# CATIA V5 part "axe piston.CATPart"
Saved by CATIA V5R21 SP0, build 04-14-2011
Part number: axe de piston
Material "Nickel": density 8880 kg/m3, Young's modulus 2.14e+11 Pa, Poisson ratio 0.31, thermal expansion 1.31e-05 1/K
Bounding box of the stored display mesh (mm): x -2.5 to 2.5, y -10 to 10, z -2.5 to 2.5
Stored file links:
  C:\Users\Olivier\Desktop\redaction CATIA (local)\CATIA\DONNEES\Exercice assemblage 2 (ensemble piston)\axe piston.CATPart
  C:\Users\Olivier\Desktop\redaction CATIA (local)\pompe à moteur de ventilation refait\Pompe_a_moteur_de_ventilation.CATProduct
  C:\Users\Olivier\Desktop\redaction CATIA (local)\pompe à moteur de ventilation refait\Ecrou a collerette M5.CATPart
  C:\Program Files\Dassault Systemes\B21\win_b64\startup\materials\French\Catalog.CATMaterial
  C:\Program Files\Dassault Systemes\B21\win_b64\startup\materials\brushed_metal1.jpg
  C:\Program Files\Dassault Systemes\B21\win_b64\startup\materials\brushed_metal2.jpg
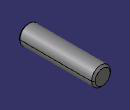
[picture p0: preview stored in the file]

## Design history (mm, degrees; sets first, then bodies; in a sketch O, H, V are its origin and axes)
Body1 (main body), material "Nickel"
  Sketch1 on zx-plane, origin (0, 0, 0), H (-1, 0, 0), V (0, 0, 1)
    circle A1 centre (0, 0) radius 2.5
  Pad1: profile Sketch1, direction (0, 1, 0), length 10, mirrored extent
  Chamfer1: length 0.5, angle 45, on face of Pad1 from Sketch1.A1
